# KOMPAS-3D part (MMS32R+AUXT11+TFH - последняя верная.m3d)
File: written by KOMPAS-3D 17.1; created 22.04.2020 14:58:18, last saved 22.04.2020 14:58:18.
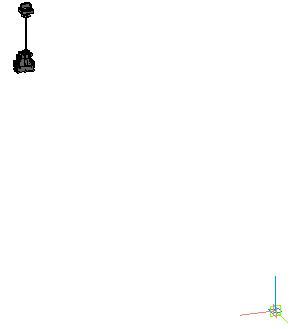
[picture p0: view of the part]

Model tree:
1. Операция без истории:1
2. Операция без истории:2
3. Операция без истории:3
4. Операция без истории:4
5. Операция без истории:5
6. Операция без истории:6
7. Операция без истории:7
8. Операция без истории:8
9. Операция без истории:9
10. Операция без истории:10
11. Операция без истории:11
12. Операция без истории:12
13. Операция без истории:13

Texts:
  2020-\X2\4EA754C1\X0\_stp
